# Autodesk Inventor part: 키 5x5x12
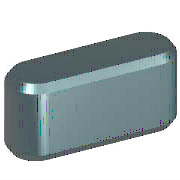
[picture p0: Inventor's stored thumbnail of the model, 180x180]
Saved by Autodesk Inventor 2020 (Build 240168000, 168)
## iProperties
IsCustomPart: 1
Created: 2012-02
Part Number: 키 5x5x12
Material: 강철, 연강
Description: 키 및 해당 키홈
Document SubType Name: Modeling
Standard: KS B 1311
Designer: mduedu
Standards Organization: KS
Language: ko-KR
Size Designation: 5 x 5 x 12
Categories: <MemberInstance><Categories><Category DisplayName="샤프트 부품" InternalName="7f7aeb1f-a693-4053-b835-cee3144e0d98" Mnemonic="SHFT"><Category DisplayName="키" Interna
Density: 1 g/cm^3
Appearance: 노란색
Author: mduedu
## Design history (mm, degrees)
workplane "Work Plane1"
workplane "Work Plane2"
sketch "스케치1"
  geometry: L1 (2.5, 2.5)-(9.5, 2.5); L2 (9.5, -2.5)-(2.5, -2.5); L3 (0, 9.4)-(0, -7.4) reference; L4 (-5, 0)-(30, 0) reference; L5 (12, 0)-(12, 7); A1 r 2.5 centre (2.5, 0) between (2.5, 2.5) and (2.5, -2.5); A2 r 2.5 centre (9.5, 0) between (9.5, -2.5) and (9.5, 2.5)
  constraints: 6 end point, 5 point on circle, 4 tangent, 3 point on line, 2 centre point, 1 horizontal, 1 parallel, 1 perpendicular
  dimensions: "d0" = 2.5 radius of A1 (= 0.5 x PB); "d13" = 2.5 radius of A2 (= 0.5 x PB); "d14" = 12 distance between parallel lines of L5 L3 (= NLG)
extrude "본체1" new body sketch "스케치1" taper "d3" = 0 deg; stored distance "d4" = 10
workplane "Work Plane3"
body "Solid1"
chamfer "모따기1" distance "d8" = 0.4 (= PHH); stored, may be unused: second distance "d9" = 0.4 (= PHH), angle "d15" = 45 deg
other parameters: "d1" = -3 (= -PNT), "d2" = 2 (= PH - PNT), "NLG" = 12 [user parameter; used in 3 equation terms], "PB" = 5 [user parameter; used in 2 equation terms], "PNT" = 3 [user parameter; used in 2 equation terms], "PH" = 5 [user parameter; used in 1 equation term], "PHH" = 0.4 [user parameter; used in 2 equation terms], "d10" = 0, "d16" = 0, "d17" = 0, "d18" = 0, "WDMIN" = 12 [user parameter], "PLB2" = 12 (= NLG) [user parameter], "WDMAX" = 17 [user parameter], "PLB1" = 12 (= NLG) [user parameter], "RR" = 0.16 [user parameter], "PUEB" = 2.3 [user parameter]
